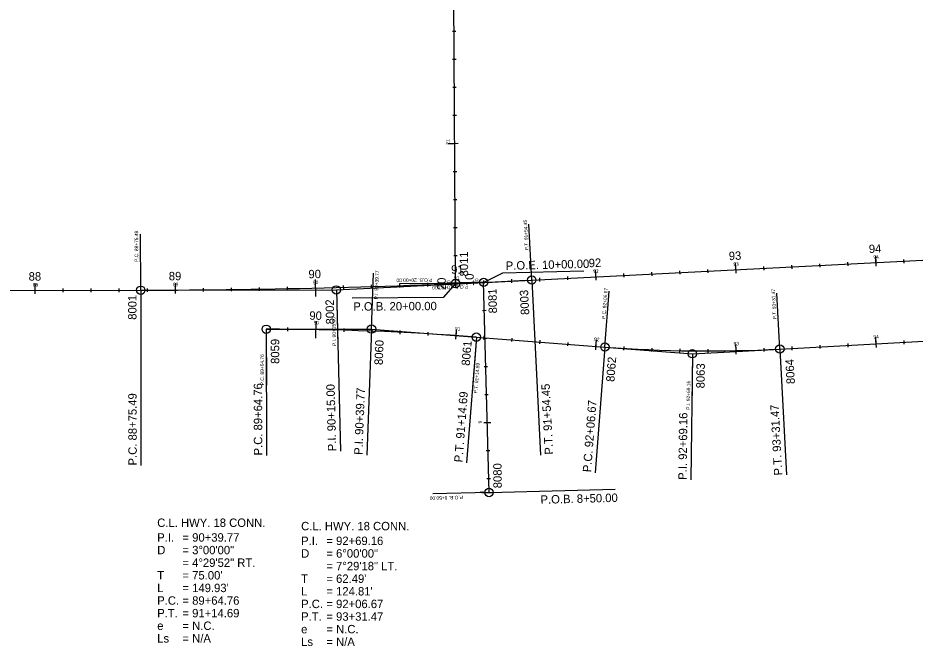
# Model space of a CAD drawing. Extents: x 1708585 to 1714116, y 541444 to 545437.
# Drawn here: x 1710798 to 1711438, y 543999 to 544448 of the extents above; entities that cross this region are included whole.
import ezdxf

# ---------------------------------------------------------------- set-up
doc = ezdxf.new("R2010")
doc.units = 0
for name, color, linetype in [('CL_Highway_1', 7, 'Continuous'), ('CL_Highway_1_40_PText', 7, 'Continuous'), ('CL_Highway_1_40_Sta', 7, 'Continuous'), ('CL_Highway_1_PText', 7, 'Continuous'), ('CL_Highway_1_Sta', 7, 'Continuous'), ('CL_Highway_1_Sta_Minor_Text', 7, 'Continuous'), ('CL_Highway_1_Tangent', 7, 'Continuous'), ('CL_XS_1', 7, 'Continuous'), ('CL_XS_1_40_PText', 7, 'Continuous'), ('CL_XS_1_40_Sta', 7, 'Continuous'), ('CL_XS_1_PText', 7, 'Continuous'), ('CL_XS_1_Sta', 7, 'Continuous'), ('CL_XS_1_Tangent', 7, 'Continuous'), ('CL_XS_2', 7, 'Continuous'), ('CL_XS_2_40_PText', 7, 'Continuous'), ('CL_XS_2_40_Sta', 7, 'Continuous'), ('CL_XS_2_PText', 7, 'Continuous'), ('CL_XS_2_Sta', 7, 'Continuous'), ('CL_XS_3', 7, 'Continuous'), ('CL_XS_3_40_PText', 7, 'Continuous'), ('CL_XS_3_40_Sta', 7, 'Continuous'), ('CL_XS_3_PText', 7, 'Continuous'), ('CL_XS_3_Sta', 7, 'Continuous'), ('CurveData_100', 7, 'Continuous'), ('Point_CL_Highway_1', 7, 'Continuous'), ('Point_CL_XS_1', 7, 'Continuous'), ('Point_CL_XS_2', 7, 'Continuous'), ('Point_CL_XS_3', 7, 'Continuous'), ('Point_Number', 7, 'Continuous')]:
    doc.layers.add(name, color=color, linetype=linetype)

msp = doc.modelspace()

# ---------------------------------------------------------------- linework, layer by layer
at = {"layer": 'CL_Highway_1'}
for p, q in [((1711164.22, 544260.55), (1712107.9, 544308.18)), ((1709809.9, 544251.39), (1710885.4, 544253.27))]:
    msp.add_line(p, q, dxfattribs=at)
msp.add_arc((1710875.38, 549982.84), 5729.58, 270.10015, 272.889665, dxfattribs=at)
at = {"layer": 'CL_Highway_1_40_PText'}
for points in [[(1711164.22, 544260.55), (1711162.21, 544300.5)], [(1710885.4, 544253.27), (1710885.33, 544293.27)], [(1711024.9, 544253.52), (1711025.94, 544213.53)]]:
    msp.add_lwpolyline(points, dxfattribs=at)
at = {"layer": 'CL_Highway_1_40_Sta'}
for points in [[(1711389.43, 544273.17), (1711389.56, 544270.67)], [(1711409.34, 544275.42), (1711409.59, 544270.43)], [(1711429.38, 544275.18), (1711429.5, 544272.69)], [(1711249.61, 544266.11), (1711249.73, 544263.61)], [(1711269.58, 544267.12), (1711269.71, 544264.62)], [(1711289.56, 544268.13), (1711289.68, 544265.63)], [(1711309.47, 544270.38), (1711309.72, 544265.39)], [(1711329.51, 544270.14), (1711329.63, 544267.65)], [(1711349.48, 544271.15), (1711349.61, 544268.65)], [(1711369.46, 544272.16), (1711369.58, 544269.66)], [(1711109.73, 544260.56), (1711109.94, 544255.56)], [(1711129.76, 544260.16), (1711129.87, 544257.67)], [(1711149.74, 544261.09), (1711149.86, 544258.59)], [(1711169.71, 544262.08), (1711169.84, 544259.58)], [(1711189.68, 544263.08), (1711189.81, 544260.59)], [(1711209.6, 544265.34), (1711209.85, 544260.35)], [(1711229.63, 544265.1), (1711229.76, 544262.6)], [(1710809.9, 544255.64), (1710809.91, 544250.64)], [(1710829.9, 544254.42), (1710829.9, 544251.92)], [(1710849.9, 544254.46), (1710849.9, 544251.96)], [(1710869.9, 544254.49), (1710869.9, 544251.99)], [(1710889.9, 544254.53), (1710889.91, 544252.03)], [(1710909.89, 544255.87), (1710909.92, 544250.87)], [(1710929.89, 544254.77), (1710929.91, 544252.27)], [(1710949.88, 544255), (1710949.92, 544252.5)], [(1710969.88, 544255.29), (1710969.92, 544252.79)], [(1710989.87, 544255.66), (1710989.92, 544253.16)], [(1711009.83, 544257.34), (1711009.95, 544252.34)], [(1711029.85, 544256.6), (1711029.92, 544254.1)], [(1711049.84, 544257.17), (1711049.91, 544254.67)], [(1711069.82, 544257.81), (1711069.91, 544255.31)], [(1711089.81, 544258.53), (1711089.9, 544256.03)]]:
    msp.add_lwpolyline(points, dxfattribs=at)
at = {"layer": 'CL_Highway_1_PText'}
for points in [[(1711164.22, 544260.55), (1711170.53, 544135.71)], [(1710885.4, 544253.27), (1710885.61, 544128.27)], [(1711024.9, 544253.52), (1711027.9, 544138.55)]]:
    msp.add_lwpolyline(points, dxfattribs=at)
at = {"layer": 'CL_Highway_1_Sta'}
for points in [[(1711309.34, 544272.88), (1711309.59, 544267.89)], [(1711409.22, 544277.92), (1711409.47, 544272.93)], [(1711209.47, 544267.84), (1711209.72, 544262.84)], [(1711009.75, 544260.84), (1711010.03, 544248.84)], [(1711109.63, 544263.06), (1711109.84, 544258.06)], [(1710809.89, 544258.14), (1710809.9, 544253.14)], [(1710909.87, 544258.37), (1710909.9, 544253.37)]]:
    msp.add_lwpolyline(points, dxfattribs=at)
at = {"layer": 'CL_Highway_1_Tangent'}
for p, q in [((1711024.9, 544253.52), (1711164.22, 544260.55)), ((1710885.4, 544253.27), (1711024.9, 544253.52))]:
    msp.add_line(p, q, dxfattribs=at)
at = {"layer": 'CL_XS_1'}
for p, q in [((1711341.12, 544211.33), (1711633.04, 544227.1)), ((1711124.71, 544219.81), (1711216.41, 544212.76))]:
    msp.add_line(p, q, dxfattribs=at)
for centre, radius, start, end in [((1710978.26, 542315.57), 1909.86, 85.60231, 90.10015), ((1711289.63, 545164.87), 954.93, 265.60231, 273.09078)]:
    msp.add_arc(centre, radius, start, end, dxfattribs=at)
at = {"layer": 'CL_XS_1_40_PText'}
for points in [[(1711049.93, 544225.56), (1711051.43, 544265.53)], [(1711216.41, 544212.76), (1711219.48, 544252.64)], [(1711341.12, 544211.33), (1711338.96, 544251.27)], [(1710974.92, 544225.43), (1710974.99, 544185.43)], [(1711124.71, 544219.81), (1711121.64, 544179.93)], [(1711278.72, 544207.96), (1711278.26, 544167.97)]]:
    msp.add_lwpolyline(points, dxfattribs=at)
at = {"layer": 'CL_XS_1_40_Sta'}
for points in [[(1711127.43, 544258.86), (1711132.43, 544258.98)], [(1711010.2, 544227.66), (1711010.12, 544222.66)], [(1710990.17, 544226.64), (1710990.15, 544224.14)], [(1711030.19, 544225.98), (1711030.12, 544223.48)], [(1711050.19, 544225.33), (1711050.09, 544222.83)], [(1711070.18, 544224.47), (1711070.06, 544221.97)], [(1711090.17, 544223.4), (1711090.02, 544220.91)], [(1711110.23, 544223.37), (1711109.88, 544218.38)], [(1711130.09, 544220.65), (1711129.9, 544218.15)], [(1711150.04, 544219.11), (1711149.84, 544216.62)], [(1711169.98, 544217.58), (1711169.79, 544215.09)], [(1711189.92, 544216.05), (1711189.73, 544213.55)], [(1711209.96, 544215.76), (1711209.57, 544210.77)], [(1711389.51, 544215.2), (1711389.64, 544212.7)], [(1711409.41, 544217.52), (1711409.68, 544212.53)], [(1711429.45, 544217.35), (1711429.59, 544214.86)], [(1711229.79, 544213.07), (1711229.63, 544210.58)], [(1711249.74, 544212.03), (1711249.63, 544209.53)], [(1711269.7, 544211.4), (1711269.65, 544208.9)], [(1711289.67, 544211.19), (1711289.67, 544208.69)], [(1711309.62, 544212.65), (1711309.72, 544207.65)], [(1711329.61, 544212.03), (1711329.71, 544209.53)], [(1711349.57, 544213.04), (1711349.7, 544210.54)], [(1711369.54, 544214.12), (1711369.67, 544211.62)]]:
    msp.add_lwpolyline(points, dxfattribs=at)
at = {"layer": 'CL_XS_1_PText'}
for points in [[(1710974.92, 544225.43), (1710975.08, 544135.43)], [(1711049.93, 544225.56), (1711046.55, 544135.62)], [(1711124.71, 544219.81), (1711117.81, 544130.07)], [(1711216.41, 544212.76), (1711209.51, 544123.02)], [(1711341.12, 544211.33), (1711345.97, 544121.46)], [(1711278.72, 544207.96), (1711277.69, 544117.97)]]:
    msp.add_lwpolyline(points, dxfattribs=at)
at = {"layer": 'CL_XS_1_Sta'}
for points in [[(1711010.26, 544231.16), (1711010.06, 544219.17)], [(1711110.36, 544225.37), (1711110.05, 544220.88)], [(1711210.11, 544217.75), (1711209.76, 544213.27)], [(1711409.3, 544219.52), (1711409.55, 544215.03)], [(1711309.58, 544214.65), (1711309.67, 544210.16)]]:
    msp.add_lwpolyline(points, dxfattribs=at)
at = {"layer": 'CL_XS_1_Tangent'}
for p, q in [((1710974.92, 544225.43), (1711049.93, 544225.56)), ((1711049.93, 544225.56), (1711124.71, 544219.81)), ((1711216.41, 544212.76), (1711278.72, 544207.96)), ((1711278.72, 544207.96), (1711341.12, 544211.33))]:
    msp.add_line(p, q, dxfattribs=at)
at = {"layer": 'CL_XS_2'}
msp.add_line((1711109.92, 544258.06), (1711107.98, 544585.51), dxfattribs=at)
at = {"layer": 'CL_XS_2_40_PText'}
msp.add_lwpolyline([(1711109.92, 544258.06), (1711069.92, 544257.83)], dxfattribs=at)
at = {"layer": 'CL_XS_2_40_Sta'}
for points in [[(1711107.6, 544438.05), (1711110.1, 544438.07)], [(1711107.72, 544418.05), (1711110.22, 544418.07)], [(1711107.84, 544398.06), (1711110.34, 544398.07)], [(1711107.96, 544378.06), (1711110.46, 544378.07)], [(1711106.83, 544358.05), (1711111.83, 544358.08)], [(1711108.2, 544338.06), (1711110.7, 544338.07)], [(1711108.32, 544318.06), (1711110.82, 544318.07)], [(1711108.43, 544298.06), (1711110.93, 544298.07)], [(1711108.55, 544278.06), (1711111.05, 544278.07)], [(1711107.42, 544258.05), (1711112.42, 544258.08)]]:
    msp.add_lwpolyline(points, dxfattribs=at)
at = {"layer": 'CL_XS_2_PText'}
msp.add_lwpolyline([(1711109.92, 544258.06), (1711101.11, 544248.01), (1711036.11, 544247.63)], dxfattribs=at)
at = {"layer": 'CL_XS_2_Sta'}
for points in [[(1711104.33, 544358.03), (1711109.33, 544358.06)], [(1711103.92, 544258.03), (1711115.92, 544258.1)]]:
    msp.add_lwpolyline(points, dxfattribs=at)
at = {"layer": 'CL_XS_3'}
msp.add_line((1711133.74, 544108.97), (1711129.93, 544258.92), dxfattribs=at)
at = {"layer": 'CL_XS_3_40_PText'}
for points in [[(1711129.93, 544258.92), (1711096.66, 544258.07)], [(1711133.74, 544108.97), (1711093.76, 544107.95)]]:
    msp.add_lwpolyline(points, dxfattribs=at)
at = {"layer": 'CL_XS_3_40_Sta'}
for points in [[(1711127.43, 544258.86), (1711132.43, 544258.98)], [(1711129.19, 544238.89), (1711131.69, 544238.96)], [(1711129.7, 544218.9), (1711132.2, 544218.96)], [(1711130.21, 544198.91), (1711132.71, 544198.97)], [(1711130.71, 544178.91), (1711133.21, 544178.98)], [(1711129.97, 544158.89), (1711134.97, 544159.02)], [(1711131.73, 544138.93), (1711134.23, 544138.99)], [(1711132.24, 544118.93), (1711134.74, 544119)], [(1711131.25, 544108.9), (1711136.24, 544109.03)]]:
    msp.add_lwpolyline(points, dxfattribs=at)
at = {"layer": 'CL_XS_3_PText'}
for points in [[(1711129.93, 544258.82), (1711143.52, 544265.68), (1711201.43, 544267.15)], [(1711133.74, 544108.97), (1711223.72, 544111.26)]]:
    msp.add_lwpolyline(points, dxfattribs=at)
at = {"layer": 'CL_XS_3_Sta'}
for points in [[(1711123.93, 544258.77), (1711135.93, 544259.07)], [(1711129.25, 544108.85), (1711133.74, 544108.97)]]:
    msp.add_lwpolyline(points, dxfattribs=at)
at = {"layer": 'Point_CL_Highway_1'}
for centre in [(1711164.22, 544260.55), (1710885.4, 544253.27), (1711024.9, 544253.52)]:
    msp.add_circle(centre, 3, dxfattribs=at)
at = {"layer": 'Point_CL_XS_1'}
for centre in [(1710974.92, 544225.43), (1711049.93, 544225.56), (1711124.71, 544219.81), (1711216.41, 544212.76), (1711278.72, 544207.96), (1711341.12, 544211.33)]:
    msp.add_circle(centre, 3, dxfattribs=at)
at = {"layer": 'Point_CL_XS_2'}
msp.add_circle((1711109.92, 544258.06), 3, dxfattribs=at)
at = {"layer": 'Point_CL_XS_3'}
for centre in [(1711129.93, 544258.92), (1711133.74, 544108.97)]:
    msp.add_circle(centre, 3, dxfattribs=at)

# ---------------------------------------------------------------- texts
at = {"layer": 'CL_Highway_1_40_PText'}
for s, rotation, p in [('P.T. 91+54.45', 92.88967, (1711161.9, 544281.78)), ('P.C. 88+75.49', 90.10015, (1710883.61, 544273.5)), ('P.I. 90+15.00', 91.49491, (1711024.69, 544213.5))]:
    msp.add_text(s, height=2.5, rotation=rotation, dxfattribs=at).set_placement(p)
at = {"layer": 'CL_Highway_1_40_Sta'}
for s, rotation, p in [('93', 2.88967, (1711307.99, 544270.56)), ('94', 2.88967, (1711407.87, 544275.6)), ('92', 2.88967, (1711208.12, 544265.52)), ('90', 1.34522, (1711008.27, 544257.55)), ('91', 2.34522, (1711108.83, 544260.77)), ('88', 0.10015, (1710808.43, 544255.89)), ('89', 0.34522, (1710908.41, 544256.11))]:
    msp.add_text(s, height=2.5, rotation=rotation, dxfattribs=at).set_placement(p)
at = {"layer": 'CL_Highway_1_PText'}
for s, rotation, p in [('P.I. 90+15.00', 91.49491, (1711024.9, 544138.48)), ('P.T. 91+54.45', 92.88967, (1711179.51, 544136.16)), ('P.C. 88+75.49', 90.10015, (1710882.61, 544128.27))]:
    msp.add_text(s, height=6, rotation=rotation, dxfattribs=at).set_placement(p)
at = {"layer": 'CL_Highway_1_Sta'}
msp.add_text('90', height=6, rotation=1.34522, dxfattribs=at).set_placement((1711005.07, 544261.73))
at = {"layer": 'CL_Highway_1_Sta_Minor_Text'}
for s, rotation, p in [('94', 2.88967, (1711404.73, 544279.7)), ('93', 2.88967, (1711304.85, 544274.66)), ('92', 2.88967, (1711204.98, 544269.61)), ('88', 0.10015, (1710805.5, 544260.13)), ('89', 0.34522, (1710905.44, 544260.34)), ('91', 2.34522, (1711106.86, 544264.95))]:
    msp.add_text(s, height=6, rotation=rotation, dxfattribs=at).set_placement(p)
at = {"layer": 'CL_XS_1_40_PText'}
for s, rotation, p in [('P.I. 90+39.77', 87.85123, (1711054.47, 544246.73)), ('P.C. 92+06.67', 85.60231, (1711216.69, 544232.7)), ('P.T. 93+31.47', 93.09078, (1711338.72, 544232.56)), ('P.C. 89+64.76', 90.10015, (1710973.24, 544185.42)), ('P.T. 91+14.69', 85.60231, (1711125.38, 544179.64)), ('P.I. 92+69.16', 89.34654, (1711277.01, 544167.98))]:
    msp.add_text(s, height=2.5, rotation=rotation, dxfattribs=at).set_placement(p)
at = {"layer": 'CL_XS_1_40_Sta'}
for s, rotation, p in [('90', 359.0431, (1711008.67, 544228.94)), ('91', 356.0431, (1711109.42, 544224.68)), ('94', 3.09078, (1711407.88, 544218.69)), ('92', 355.60231, (1711208.59, 544217.12)), ('93', 1.20233, (1711308.13, 544213.87))]:
    msp.add_text(s, height=2.5, rotation=rotation, dxfattribs=at).set_placement(p)
at = {"layer": 'CL_XS_1_PText'}
for s, rotation, p in [('P.C. 89+64.76', 90.10015, (1710972.08, 544135.42)), ('P.I. 90+39.77', 87.84769, (1711043.55, 544135.73)), ('P.T. 91+14.69', 85.60231, (1711114.82, 544130.3)), ('P.C. 92+06.67', 85.60231, (1711206.52, 544123.25)), ('P.T. 93+31.47', 93.09078, (1711342.98, 544121.3)), ('P.I. 92+69.16', 89.34654, (1711274.69, 544118))]:
    msp.add_text(s, height=6, rotation=rotation, dxfattribs=at).set_placement(p)
at = {"layer": 'CL_XS_1_Sta'}
msp.add_text('90', height=6, rotation=359.0431, dxfattribs=at).set_placement((1711005.62, 544232.24))
at = {"layer": 'CL_XS_2_40_PText'}
msp.add_text('P.O.B. 20+00.00', height=2.5, rotation=180.33927, dxfattribs=at).set_placement((1711093.38, 544261.72))
at = {"layer": 'CL_XS_2_40_Sta'}
for s, p in [('21', (1711105.58, 544357.14)), ('20', (1711106.18, 544256.49))]:
    msp.add_text(s, height=2.5, rotation=90.33927, dxfattribs=at).set_placement(p)
at = {"layer": 'CL_XS_2_PText'}
msp.add_text('P.O.B. 20+00.00', height=6, rotation=0.33927, dxfattribs=at).set_placement((1711036.99, 544238.67))
at = {"layer": 'CL_XS_2_Sta'}
msp.add_text('20', height=6, rotation=90.33927, dxfattribs=at).set_placement((1711102.95, 544253.37))
at = {"layer": 'CL_XS_3_40_PText'}
for s, p in [('P.O.E. 10+00.00', (1711118.87, 544256.89)), ('P.O.B. 8+50.00', (1711115.17, 544106.75))]:
    msp.add_text(s, height=2.5, rotation=181.4573, dxfattribs=at).set_placement(p)
at = {"layer": 'CL_XS_3_40_Sta'}
for s, p in [('10', (1711126.21, 544257.84)), ('9', (1711128.74, 544158.28)), ('8', (1711130.01, 544108.31))]:
    msp.add_text(s, height=2.5, rotation=91.4573, dxfattribs=at).set_placement(p)
at = {"layer": 'CL_XS_3_PText'}
for s, p in [('P.O.E. 10+00.00', (1711145.76, 544267.74)), ('P.O.B. 8+50.00', (1711170.54, 544100.9))]:
    msp.add_text(s, height=6, rotation=1.4573, dxfattribs=at).set_placement(p)
at = {"layer": 'CL_XS_3_Sta'}
msp.add_text('10', height=6, rotation=91.4573, dxfattribs=at).set_placement((1711122.99, 544256.28))
at = {"layer": 'CurveData_100'}
for s, p in [('C.L. HWY. 18 CONN.', (1710897.18, 544084.41)), ('C.L. HWY. 18 CONN.', (1710999.79, 544082)), ('P.I.', (1710897.18, 544073.91)), ('= 90+39.77', (1710915.18, 544073.91)), ('P.I.', (1710999.79, 544071.5)), ('= 92+69.16', (1711017.79, 544071.5)), ('D', (1710897.18, 544064.91)), ('= 3%%d00\'00"', (1710915.18, 544064.91)), ('D', (1710999.79, 544062.5)), ('= 6%%d00\'00"', (1711017.79, 544062.5)), ('= 4%%d29\'52" RT.', (1710915.18, 544055.91)), ('= 7%%d29\'18" LT.', (1711017.79, 544053.5)), ('T', (1710897.18, 544046.91)), ("= 75.00'", (1710915.18, 544046.91)), ('T', (1710999.79, 544044.5)), ("= 62.49'", (1711017.79, 544044.5)), ('L', (1710897.18, 544037.91)), ("= 149.93'", (1710915.18, 544037.91)), ('L', (1710999.79, 544035.5)), ("= 124.81'", (1711017.79, 544035.5)), ('P.C.', (1710897.18, 544028.91)), ('= 89+64.76', (1710915.18, 544028.91)), ('P.C.', (1710999.79, 544026.5)), ('= 92+06.67', (1711017.79, 544026.5)), ('P.T.', (1710897.18, 544019.91)), ('= 91+14.69', (1710915.18, 544019.91)), ('P.T.', (1710999.79, 544017.5)), ('= 93+31.47', (1711017.79, 544017.5)), ('= N.C.', (1710915.18, 544010.91)), ('e', (1710897.18, 544010.91)), ('e', (1710999.79, 544008.5)), ('= N.C.', (1711017.79, 544008.5)), ('Ls', (1710897.18, 544001.91)), ('= N/A', (1710915.18, 544001.91)), ('Ls', (1710999.79, 543999.5)), ('= N/A', (1711017.79, 543999.5))]:
    msp.add_text(s, height=6, dxfattribs=at).set_placement(p)
at = {"layer": 'Point_Number'}
for s, rotation, p in [('8011', 90.33927, (1711118.89, 544263.12)), ('8081', 91.4573, (1711139.5, 544236.8)), ('8003', 92.88967, (1711162.47, 544235.82)), ('8001', 90, (1710882.4, 544232.17)), ('8002', 91.39476, (1711023.5, 544228.97)), ('8059', 90.10015, (1710984.2, 544200.72)), ('8060', 87.85123, (1711057.97, 544199.83)), ('8061', 85.3631, (1711120.03, 544199.21)), ('8062', 85.60231, (1711223.12, 544187.73)), ('8064', 93.09078, (1711351.87, 544186.47)), ('8063', 89.34654, (1711287.44, 544183.22)), ('8080', 90.33927, (1711142.83, 544112.02))]:
    msp.add_text(s, height=6, rotation=rotation, dxfattribs=at).set_placement(p)

doc.saveas('drawing.dxf')
